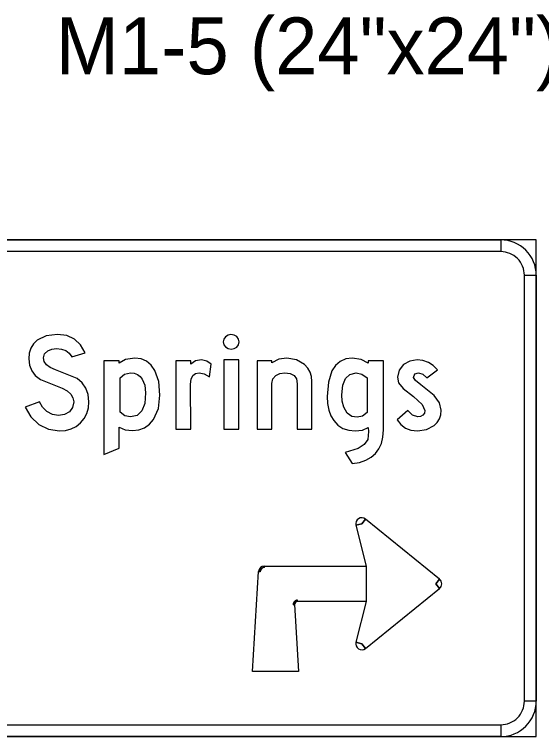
# Model space of a CAD drawing. Extents: x 620864 to 620948.6, y 415499.7 to 415559.1.
# Drawn here: x 620869.9 to 620873.61, y 415523.96 to 415529.05 of the extents above; entities that cross this region are included whole.
import ezdxf

# ---------------------------------------------------------------- set-up
doc = ezdxf.new("R2010")
doc.units = 0
doc.layers.add('SIGNS', color=7, linetype='Continuous')

msp = doc.modelspace()

# ---------------------------------------------------------------- linework, layer by layer
at = {"layer": 'SIGNS'}
for p, q in [((620873.5731, 415527.462), (620864.0731, 415527.462)), ((620873.3231, 415527.462), (620873.3231, 415527.3787)), ((620873.5731, 415523.962), (620873.5731, 415527.462)), ((620873.4898, 415527.212), (620873.5731, 415527.212)), ((620872.3448, 415525.4612), (620872.3715, 415525.4942)), ((620872.3036, 415525.4508), (620872.3448, 415525.4612)), ((620871.6591, 415525.1524), (620871.6591, 415525.1637)), ((620871.6175, 415525.1245), (620871.6288, 415525.1239)), ((620872.8924, 415525.0717), (620872.8656, 415525.0387)), ((620872.8656, 415525.0387), (620872.8924, 415525.0057)), ((620871.8616, 415524.891), (620871.8712, 415524.8916)), ((620871.892, 415524.9137), (620871.892, 415524.9233)), ((620872.3448, 415524.6162), (620872.3036, 415524.6266)), ((620872.3715, 415524.5832), (620872.3448, 415524.6162)), ((620873.5731, 415524.212), (620873.4898, 415524.212)), ((620873.3231, 415524.0454), (620873.3231, 415523.962)), ((620864.0731, 415523.962), (620873.5731, 415523.962))]:
    msp.add_line(p, q, dxfattribs=at)
for points in [[(620873.3231, 415527.3787), (620864.3231, 415527.3787), (620864.3231, 415527.462), (620873.3231, 415527.462), (620873.3231, 415527.3787), (620873.3231, 415527.3787)], [(620873.4898, 415524.212), (620873.4898, 415527.212), (620873.5731, 415527.212), (620873.5731, 415524.212), (620873.4898, 415524.212), (620873.4898, 415524.212)], [(620869.9748, 415526.2839), (620870.0132, 415526.2154), (620870.0697, 415526.1619), (620870.1386, 415526.1273), (620870.2153, 415526.1159), (620870.2586, 415526.1193), (620870.298, 415526.1301), (620870.3333, 415526.1477), (620870.3646, 415526.173), (620870.39, 415526.2036), (620870.4084, 415526.2386), (620870.4193, 415526.2779), (620870.423, 415526.3216), (620870.4178, 415526.3731), (620870.4024, 415526.4175), (620870.3765, 415526.455), (620870.3407, 415526.4855), (620870.1871, 415526.5455), (620870.1506, 415526.5617), (620870.1246, 415526.5814), (620870.109, 415526.6038), (620870.1039, 415526.6297), (620870.1113, 415526.6583), (620870.1342, 415526.6805), (620870.162, 415526.6923), (620870.1942, 415526.6964), (620870.2307, 415526.6926), (620870.2612, 415526.6818), (620870.2852, 415526.6635), (620870.303, 415526.6383), (620870.396, 415526.6652), (620870.3643, 415526.722), (620870.3214, 415526.7627), (620870.2672, 415526.7872), (620870.2015, 415526.7954), (620870.1216, 415526.7851), (620870.0591, 415526.7548), (620870.033, 415526.7292), (620870.0146, 415526.6992), (620870.0034, 415526.6643), (620869.9997, 415526.6246), (620870.0048, 415526.5792), (620870.0202, 415526.5398), (620870.0456, 415526.5063), (620870.0815, 415526.4788), (620870.2345, 415526.4174), (620870.2702, 415526.3981), (620870.2958, 415526.3757), (620870.311, 415526.3498), (620870.3162, 415526.3206), (620870.3087, 415526.2799), (620870.2862, 415526.2499), (620870.2519, 415526.2312), (620870.2095, 415526.2251), (620870.1672, 415526.2318), (620870.128, 415526.2522), (620870.0955, 415526.2831), (620870.0743, 415526.3212)], [(620871.4235, 415526.7954), (620871.4033, 415526.7911), (620871.3851, 415526.7791), (620871.3722, 415526.7618), (620871.3681, 415526.7429), (620871.3722, 415526.7232), (620871.3851, 415526.7072), (620871.4037, 415526.6964), (620871.4254, 415526.6928), (620871.4468, 415526.6962), (620871.4646, 415526.7068), (620871.4767, 415526.7228), (620871.4808, 415526.7435), (620871.4767, 415526.7631), (620871.464, 415526.7799), (620871.4454, 415526.7913)], [(620871.0348, 415526.1287), (620871.1403, 415526.1287), (620871.1395, 415526.4458), (620871.1431, 415526.4803), (620871.1543, 415526.5051), (620871.1728, 415526.5199), (620871.1988, 415526.5249), (620871.2345, 415526.5179), (620871.2715, 415526.4973), (620871.2853, 415526.5852), (620871.2538, 415526.608), (620871.2154, 415526.6158), (620871.1747, 415526.6086), (620871.1403, 415526.587), (620871.1403, 415526.6101), (620871.0348, 415526.6101)], [(620871.3727, 415526.1287), (620871.4782, 415526.1287), (620871.4782, 415526.6158), (620871.3727, 415526.6158)], [(620871.6081, 415526.1287), (620871.7106, 415526.1287), (620871.7106, 415526.449), (620871.7178, 415526.4818), (620871.7401, 415526.507), (620871.7685, 415526.5209), (620871.804, 415526.5255), (620871.8414, 415526.5205), (620871.8685, 415526.5061), (620871.8847, 415526.4821), (620871.8901, 415526.4484), (620871.8901, 415526.1287), (620871.9937, 415526.1287), (620871.9937, 415526.464), (620871.9903, 415526.4988), (620871.9805, 415526.5305), (620871.9638, 415526.5587), (620871.941, 415526.584), (620871.8845, 415526.6175), (620871.817, 415526.6287), (620871.7613, 415526.6201), (620871.7108, 415526.5942), (620871.7108, 415526.6101), (620871.6081, 415526.6101)], [(620872.5948, 415526.1945), (620872.6204, 415526.16), (620872.6528, 415526.1355), (620872.6913, 415526.1207), (620872.7365, 415526.1159), (620872.8011, 415526.1251), (620872.854, 415526.1531), (620872.876, 415526.1749), (620872.8918, 415526.2006), (620872.9014, 415526.2296), (620872.9047, 415526.2625), (620872.8918, 415526.3138), (620872.854, 415526.365), (620872.7602, 415526.4404), (620872.7221, 415526.4716), (620872.7095, 415526.4929), (620872.7179, 415526.5169), (620872.7438, 415526.5249), (620872.7744, 415526.5157), (620872.8037, 415526.4886), (620872.8782, 415526.5465), (620872.8475, 415526.5768), (620872.8135, 415526.5984), (620872.7756, 415526.6115), (620872.7346, 415526.6158), (620872.6825, 415526.6076), (620872.639, 415526.5832), (620872.6071, 415526.5433), (620872.5967, 415526.494), (620872.604, 415526.4536), (620872.6362, 415526.4145), (620872.7081, 415526.3571), (620872.7694, 415526.3021), (620872.7898, 415526.2587), (620872.786, 415526.2408), (620872.7746, 415526.227), (620872.7582, 415526.218), (620872.7391, 415526.215), (620872.7021, 415526.2258), (620872.6692, 415526.2585)], [(620872.8656, 415525.0387), (620872.8924, 415525.0717), (620872.3715, 415525.4942), (620872.3448, 415525.4612), (620872.3036, 415525.4508), (620872.3764, 415525.1637), (620872.3764, 415524.9137), (620872.3036, 415524.6266), (620872.3448, 415524.6162), (620872.3715, 415524.5832), (620872.8924, 415525.0057), (620872.8656, 415525.0387), (620872.8656, 415525.0387)], [(620871.8998, 415524.4204), (620871.5748, 415524.4204), (620871.6175, 415525.1245), (620871.6591, 415525.1637), (620872.3764, 415525.1637), (620872.3764, 415524.9137), (620871.892, 415524.9137), (620871.8698, 415524.9137), (620871.8712, 415524.8916), (620871.8998, 415524.4204), (620871.8998, 415524.4204)], [(620864.3231, 415524.0454), (620873.3231, 415524.0454), (620873.3231, 415523.962), (620864.3231, 415523.962), (620864.3231, 415524.0454), (620864.3231, 415524.0454)]]:
    msp.add_lwpolyline(points, close=True, dxfattribs=at)
for points in [[(620870.5281, 415525.9493), (620870.6362, 415525.9943), (620870.6362, 415526.1431), (620870.6789, 415526.1243), (620870.7306, 415526.1181), (620870.7758, 415526.1229), (620870.8157, 415526.1377), (620870.85, 415526.1622), (620870.8788, 415526.1967), (620870.9125, 415526.2729), (620870.9237, 415526.3667), (620870.9145, 415526.4632), (620870.8875, 415526.5413), (620870.8612, 415526.5794), (620870.829, 415526.6068), (620870.7903, 415526.6231), (620870.7456, 415526.6287), (620870.6819, 415526.6198), (620870.6362, 415526.5934), (620870.6362, 415526.6101), (620870.5281, 415526.6101), (620870.5281, 415525.9493)], [(620872.2266, 415525.9641), (620872.2766, 415525.8851), (620872.3282, 415525.894), (620872.373, 415525.909), (620872.4109, 415525.9298), (620872.4419, 415525.9568), (620872.4658, 415525.9893), (620872.4832, 415526.028), (620872.4934, 415526.0725), (620872.497, 415526.1232), (620872.497, 415526.6101), (620872.3908, 415526.6101), (620872.3908, 415526.5934), (620872.3402, 415526.6198), (620872.2769, 415526.6287), (620872.2316, 415526.6228), (620872.1929, 415526.6058), (620872.1607, 415526.5774), (620872.135, 415526.5379), (620872.1098, 415526.4586), (620872.1014, 415526.3584), (620872.1042, 415526.308), (620872.113, 415526.2629), (620872.1276, 415526.2228), (620872.1483, 415526.1882), (620872.1771, 415526.1561), (620872.2119, 415526.1335), (620872.2526, 415526.1199), (620872.2993, 415526.1155), (620872.3498, 415526.1215), (620872.3908, 415526.1399), (620872.3928, 415526.1117), (620872.3863, 415526.0551), (620872.3626, 415526.0197), (620872.3183, 415525.9917), (620872.2266, 415525.9641)], [(620870.6434, 415526.2474), (620870.6434, 415526.49), (620870.6733, 415526.5161), (620870.7156, 415526.5249), (620870.7416, 415526.5221), (620870.7643, 415526.5137), (620870.7833, 415526.4996), (620870.7991, 415526.48), (620870.8169, 415526.4374), (620870.8229, 415526.3845), (620870.8161, 415526.3099), (620870.7963, 415526.2569), (620870.7632, 415526.2251), (620870.717, 415526.2144), (620870.6763, 415526.2226), (620870.6434, 415526.2474)], [(620872.3834, 415526.2448), (620872.3504, 415526.22), (620872.3133, 415526.2118), (620872.2735, 415526.217), (620872.2418, 415526.24), (620872.2189, 415526.2824), (620872.2075, 415526.3247), (620872.204, 415526.3706), (620872.2102, 415526.4375), (620872.229, 415526.4855), (620872.2603, 415526.5141), (620872.3041, 415526.5237), (620872.3458, 415526.5151), (620872.3834, 415526.4895), (620872.3834, 415526.2448)]]:
    msp.add_lwpolyline(points, dxfattribs=at)
for centre, radius, start, end in [((620873.3231, 415527.212), 0.25, 0, 90.0002), ((620873.3231, 415527.212), 0.1667, 0, 90.0002), ((620872.3448, 415525.4612), 0.0425, 50.951, 194.2424), ((620871.6591, 415525.122), 0.0417, 90.0002, 176.5294), ((620871.6591, 415525.122), 0.0303, 90.0002, 176.5294), ((620872.8656, 415525.0387), 0.0425, 309.0489, 50.9511), ((620871.892, 415524.8929), 0.0304, 90.0002, 183.4708), ((620871.892, 415524.8929), 0.0208, 90.0002, 183.4708), ((620872.3448, 415524.6162), 0.0425, 165.7573, 309.0489), ((620873.3231, 415524.212), 0.25, 270.0001, 0.0003), ((620873.3231, 415524.212), 0.1667, 270.0001, 0.0003)]:
    msp.add_arc(centre, radius, start, end, dxfattribs=at)

# ---------------------------------------------------------------- texts
msp.add_text('M1-5 (24"x24")', height=0.4, rotation=0, dxfattribs=at).set_placement((620870.1891, 415528.6288))

doc.saveas('drawing.dxf')
